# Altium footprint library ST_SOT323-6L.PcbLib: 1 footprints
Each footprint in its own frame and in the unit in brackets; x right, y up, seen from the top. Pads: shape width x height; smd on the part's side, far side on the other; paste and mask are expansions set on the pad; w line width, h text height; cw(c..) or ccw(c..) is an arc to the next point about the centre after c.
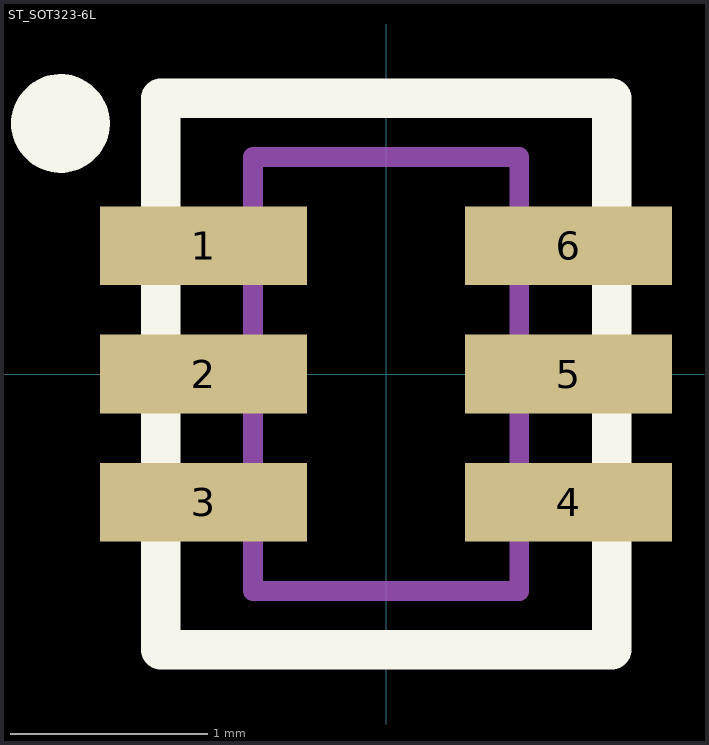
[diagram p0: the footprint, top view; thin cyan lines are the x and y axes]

## ST_SOT323-6L [mm]
height 1.1
pads (6):
  rect 1.05x0.4 smd: 1(-0.925,0.65) 2(-0.925,0) 3(-0.925,-0.65) 4(0.925,-0.65) 5(0.925,0) 6(0.925,0.65)
Top Overlay:
  circle w0.25: c-1.651,1.27 r0.125
  lines w0.2: -1.143,-1.397 1.143,-1.397 1.143,1.397 -1.143,1.397 -1.143,-1.397
Mechanical 13:
  lines w0.1: -0.675,-1.1 -0.675,1.1 0.675,1.1 0.675,-1.1 -0.675,-1.1
3D body "ST_SOT323-6L.step": height 1.1, standoff 0, extent -1.3,-1.1 1.3,1.1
